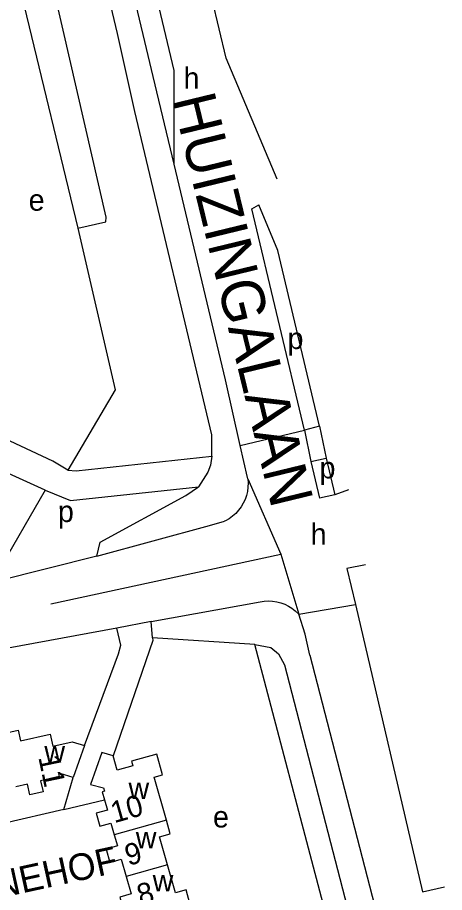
# Model space of a CAD drawing. Extents: x 157768 to 159790, y 387230 to 389604.
# Drawn here: x 159590.4 to 159670.1, y 388182.9 to 388346.4 of the extents above; entities that cross this region are included whole.
import ezdxf

# ---------------------------------------------------------------- set-up
doc = ezdxf.new("R2010")
doc.units = 0
for name, color, linetype in [('BLT_Basislijn', 7, 'Continuous'), ('BLT_Bebouwing', 7, 'Continuous'), ('BLT_Centroide', 7, 'Continuous'), ('BLT_Huisnummer', 7, 'Continuous'), ('BLT_Onderverdeling_panden', 7, 'Continuous'), ('BLT_Straatnaam', 7, 'Continuous'), ('BLT_Straatnaam_hoofdweg', 7, 'Continuous'), ('BLT_Vlakafsluiter', 7, 'Continuous')]:
    doc.layers.add(name, color=color, linetype=linetype)

msp = doc.modelspace()

# ---------------------------------------------------------------- linework, layer by layer
at = {"layer": 'BLT_Basislijn'}
for p, q in [((159619.68, 388319.03), (159615.79, 388335.38)), ((159646.8, 388270.03), (159644.04, 388269.26)), ((159644.04, 388269.26), (159645.18, 388263.41)), ((159646.8, 388270.03), (159648.06, 388264.05)), ((159595.58, 388258.06), (159581.71, 388264.36)), ((159645.18, 388263.41), (159648.06, 388264.05)), ((159648.06, 388264.05), (159649.68, 388257.23)), ((159645.18, 388263.41), (159646.8, 388256.58)), ((159595.58, 388258.06), (159585.61, 388240.77)), ((159649.68, 388257.23), (159646.8, 388256.58)), ((159626.26, 388251.49), (159629.11, 388252.25)), ((159605.24, 388245.74), (159626.26, 388251.49)), ((159605.24, 388245.74), (159585.61, 388240.77)), ((159596.64, 388236.84), (159639.59, 388246.09)), ((159651.92, 388243.41), (159653.51, 388236.7)), ((159615.41, 388233.5), (159635.74, 388237.21)), ((159653.51, 388236.7), (159666.03, 388182.96)), ((159615.41, 388233.5), (159608.96, 388232.28)), ((159615.66, 388230.49), (159615.41, 388233.5)), ((159634.76, 388229.2), (159615.66, 388230.49)), ((159599.11, 388198.4), (159600.85, 388204.35)), ((159599.11, 388198.4), (159606.68, 388200.21))]:
    msp.add_line(p, q, dxfattribs=at)
for points in [[(159638.9, 388316.22), (159629.41, 388338.86), (159590.2, 388503.39), (159579.29, 388551.84), (159555.3, 388654.47)], [(159626.71, 388264.44), (159626.71, 388268.42), (159612.32, 388328.87), (159609.1, 388343.47), (159593.56, 388408.98), (159591.48, 388418.81), (159572.28, 388500), (159537.3, 388651.19), (159506.21, 388653.51), (159502.64, 388653.24)], [(159615.79, 388335.38), (159576.57, 388500), (159565.64, 388548.48), (159542.74, 388646.48)], [(159619.68, 388319.03), (159619.68, 388336.54), (159580.46, 388501.13), (159569.54, 388549.6), (159546.63, 388647.62)], [(159601.7, 388307.08), (159606.94, 388308.26), (159607.02, 388309.1), (159590.75, 388379.87)], [(159576.09, 388345.23), (159591.71, 388348.58), (159601.7, 388307.08)], [(159632.03, 388266.45), (159629.27, 388278.67), (159619.68, 388319.03)], [(159644.04, 388269.26), (159634.17, 388310.68), (159635.49, 388311.42)], [(159646.8, 388270.03), (159639.06, 388302.9), (159635.49, 388311.42)], [(159601.7, 388307.08), (159608.68, 388276.83), (159599.86, 388261.84)], [(159599.86, 388261.84), (159597.01, 388263.47), (159581.07, 388270.95)], [(159633.41, 388260.2), (159633.39, 388260.41), (159632.03, 388266.45)], [(159599.86, 388261.84), (159601.36, 388261.68), (159626.71, 388264.44)], [(159626.71, 388264.44), (159626.49, 388262.73), (159625.95, 388261.43), (159624.25, 388258.7)], [(159595.58, 388258.06), (159600.35, 388256.16), (159624.25, 388258.7)], [(159605.24, 388245.74), (159605.87, 388248.34), (159621.89, 388257.08), (159624.25, 388258.7)], [(159633.41, 388260.2), (159633.47, 388259.42), (159633.45, 388258.63), (159633.35, 388257.85), (159633.17, 388257.08), (159632.91, 388256.34), (159632.58, 388255.62), (159632.18, 388254.95), (159631.71, 388254.31), (159631.18, 388253.73), (159630.6, 388253.2), (159629.96, 388252.74), (159629.28, 388252.34), (159629.11, 388252.25)], [(159635.74, 388237.21), (159636.51, 388237.33), (159637.29, 388237.38), (159638.07, 388237.34), (159638.84, 388237.22), (159639.59, 388237.02), (159640.32, 388236.75), (159641.02, 388236.41), (159641.68, 388235.99), (159642.29, 388235.51), (159642.94, 388234.87)], [(159644.98, 388227.24), (159644.11, 388231.17), (159642.94, 388234.87)], [(159608.96, 388232.28), (159560.57, 388223.38), (159512.1, 388212.19)], [(159602.94, 388210.37), (159609.32, 388227.5), (159609.7, 388229.07), (159608.96, 388232.28)], [(159615.66, 388230.49), (159615.71, 388229.96), (159608.3, 388208.38)], [(159644.96, 388176.75), (159647.78, 388179.06), (159647.53, 388180.76), (159634.76, 388229.2)], [(159634.76, 388229.2), (159637.72, 388228.69), (159639.15, 388227.48), (159640.29, 388225.39), (159659.19, 388152.25)], [(159644.98, 388227.24), (159664.03, 388153.5)], [(159599.11, 388198.4), (159587.82, 388195.73), (159584.4, 388197.8), (159583.36, 388198.04), (159551.21, 388190.36), (159549.47, 388186.55), (159549.17, 388184.9), (159554.58, 388160.63), (159549.27, 388159.39)]]:
    msp.add_lwpolyline(points, dxfattribs=at)
at = {"layer": 'BLT_Bebouwing'}
msp.add_line((159602.94, 388210.37), (159600.85, 388204.35), dxfattribs=at)
for points in [[(159587.85, 388212.6), (159590.56, 388213.22), (159591.02, 388211.2)], [(159591.02, 388211.2), (159596.53, 388212.46), (159597.04, 388210.22), (159600.66, 388211.04), (159602.94, 388210.37)], [(159608.3, 388208.38), (159606.17, 388209.05), (159604.08, 388203.04), (159606.48, 388202.43), (159606.65, 388201.82), (159606.26, 388201.7), (159606.68, 388200.21)], [(159618.23, 388196.38), (159615.96, 388204.43), (159617.51, 388204.87), (159616.43, 388208.72), (159611.73, 388207.4), (159611.85, 388206.97), (159611.97, 388206.54), (159609.05, 388205.72), (159608.3, 388208.38)], [(159600.85, 388204.35), (159598.42, 388205.1), (159598.1, 388205.03), (159598.21, 388204.55), (159594.76, 388203.76), (159595.24, 388201.65), (159592.76, 388201.09), (159592.3, 388203.1), (159590.12, 388202.6)], [(159606.68, 388200.21), (159607.24, 388198.25), (159605.14, 388197.66), (159605.81, 388195.27), (159607.87, 388195.85), (159608.49, 388193.64)], [(159618.44, 388188.03), (159616.97, 388193.24), (159618.96, 388193.8), (159618.23, 388196.38)], [(159608.49, 388193.64), (159609.08, 388191.57), (159606.99, 388190.98), (159607.69, 388188.48), (159609.81, 388189.08), (159610.72, 388185.85)], [(159622.61, 388180.83), (159621.9, 388183.38), (159619.91, 388182.82), (159618.44, 388188.03)], [(159610.72, 388185.85), (159611.64, 388182.58), (159609.52, 388181.98), (159610.19, 388179.61), (159612.31, 388180.21), (159612.9, 388178.1)]]:
    msp.add_lwpolyline(points, dxfattribs=at)
at = {"layer": 'BLT_Onderverdeling_panden'}
for p, q in [((159618.23, 388196.38), (159608.49, 388193.64)), ((159618.44, 388188.03), (159610.72, 388185.85))]:
    msp.add_line(p, q, dxfattribs=at)
at = {"layer": 'BLT_Vlakafsluiter'}
for p, q in [((159632.03, 388266.45), (159644.04, 388269.26)), ((159633.41, 388260.2), (159639.59, 388246.09)), ((159652.21, 388258.15), (159649.68, 388257.23)), ((159639.59, 388246.09), (159642.94, 388234.87)), ((159655.41, 388244.13), (159651.92, 388243.41)), ((159642.94, 388234.87), (159653.51, 388236.7)), ((159666.03, 388182.96), (159670.15, 388183.94))]:
    msp.add_line(p, q, dxfattribs=at)

# ---------------------------------------------------------------- texts
at = {"layer": 'BLT_Centroide'}
for s, p in [('h', (159621.43, 388333.1)), ('e', (159592.52, 388310.31)), ('p', (159640.85, 388284.45)), ('p', (159646.82, 388260.27)), ('p', (159597.98, 388252.11)), ('h', (159645.16, 388247.87)), ('w', (159595.45, 388207.16)), ('w', (159611.16, 388200.34)), ('e', (159626.93, 388195.01)), ('w', (159612.52, 388191.12)), ('w', (159615.67, 388183.06))]:
    msp.add_text(s, height=4, dxfattribs=at).set_placement(p)
at = {"layer": 'BLT_Huisnummer'}
for s, rotation, p in [('11', 281.8367, (159594.31, 388208.15)), ('10', 15.7285, (159608.49, 388195.8)), ('9', 15.7285, (159611.13, 388187.81)), ('8', 15.7285, (159613.4, 388180.36))]:
    msp.add_text(s, height=4, rotation=rotation, dxfattribs=at).set_placement(p)
at = {"layer": 'BLT_Straatnaam'}
msp.add_text('CHAMPAGNEHOF', height=5, rotation=12.3758, dxfattribs=at).set_placement((159553.59, 388174.42))
at = {"layer": 'BLT_Straatnaam_hoofdweg'}
msp.add_text('HUIZINGALAAN', height=8, rotation=283.6478, dxfattribs=at).set_placement((159619.31, 388331.23))

doc.saveas('drawing.dxf')
